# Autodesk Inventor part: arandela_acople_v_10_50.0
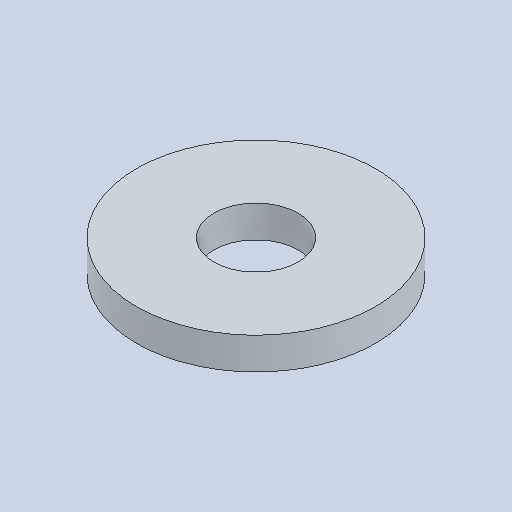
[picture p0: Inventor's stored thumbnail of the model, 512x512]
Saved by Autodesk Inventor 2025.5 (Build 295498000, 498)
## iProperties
Created: 2026-10
Part Number: arandela_acople_v_10_50.0
Material: Genérico
Document SubType Name: Modeling
Designer: Luis M
Density: 1 g/cm^3
Appearance: Valor por defecto
Author: Luis M
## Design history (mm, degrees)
feature "Base1"
node "Sólido1"
